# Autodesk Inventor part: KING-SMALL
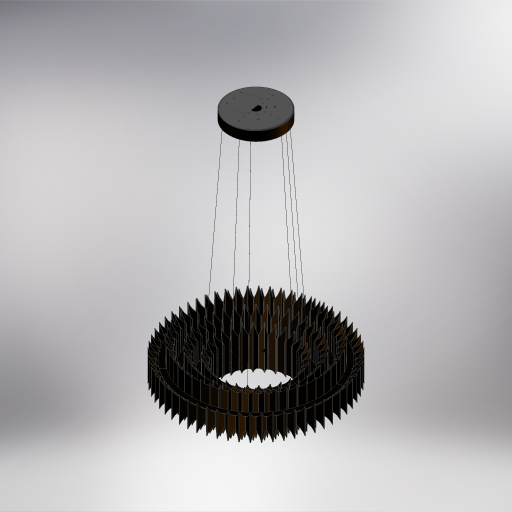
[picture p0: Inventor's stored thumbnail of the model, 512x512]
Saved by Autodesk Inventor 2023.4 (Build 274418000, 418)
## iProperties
Created: 2024-05
Part Number: KING-SMALL
Material: Generic
Document SubType Name: Modeling
Designer: JM
Density: 1 g/cm^3
Appearance: Default
Author: JM
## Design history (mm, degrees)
derived "KING-SMALL-0001-CUSTOMER.iam"
body "Solid1"
node "KINX-0008 - Ring size 4.iam:1::KINX0008.1 - Ring size 4.ipt:"
body "Solid2"
body "Solid3"
body "Solid4"
body "Solid5"
body "Solid6"
node "KINX-0006 - Ring size 2.iam:1::KINX0006.1 - Ring size 2.ipt:"
body "Solid7"
body "Solid8"
body "Solid9"
body "Solid10"
body "Solid11"
body "Solid12"
node "KINX-0007 - Ring size 3.iam:1::KINX0007.1 - Ring size 3.ipt:"
body "Solid13"
body "Solid14"
body "Solid15"
body "Solid16"
body "Solid17"
body "Solid18"
node "KINX-0011 - Ring top cover - size 4 - 811mm dia.ipt:1"
body "Solid19"
node "KINX-0010 - Ring top cover - size 3 - 663mm dia.ipt:1"
body "Solid20"
node "KINX-0009 - Ring top cover - size 2 - 517mm dia.ipt:1"
body "Solid21"
node "KINX-0011 - Ring top cover - size 4 - 811mm dia.ipt:2"
body "Solid22"
node "KINX-0010 - Ring top cover - size 3 - 663mm dia.ipt:2"
body "Solid23"
node "KINX-0009 - Ring top cover - size 2 - 517mm dia.ipt:2"
body "Solid24"
node "KINX-0011 - Ring top cover - size 4 - 811mm dia.ipt:3"
body "Solid25"
node "KINX-0010 - Ring top cover - size 3 - 663mm dia.ipt:3"
body "Solid26"
node "KINX-0009 - Ring top cover - size 2 - 517mm dia.ipt:3"
body "Solid27"
node "KINX-0011 - Ring top cover - size 4 - 811mm dia.ipt:4"
body "Solid28"
node "KINX-0010 - Ring top cover - size 3 - 663mm dia.ipt:4"
body "Solid29"
node "KINX-0009 - Ring top cover - size 2 - 517mm dia.ipt:4"
body "Solid30"
node "KINX-0011 - Ring top cover - size 4 - 811mm dia.ipt:5"
body "Solid31"
node "KINX-0010 - Ring top cover - size 3 - 663mm dia.ipt:5"
body "Solid32"
node "KINX-0009 - Ring top cover - size 2 - 517mm dia.ipt:5"
body "Solid33"
body "Solid34"
node "KINX-AS09 - Ceiling Rose - CUSTOMERCAD.iam:1::tensile-grip-0"
body "Solid35"
node "KINX-AS09 - Ceiling Rose - CUSTOMERCAD.iam:1::tensile-grip-0"
body "Solid36"
node "KINX-AS09 - Ceiling Rose - CUSTOMERCAD.iam:1::tensile-grip-0"
body "Solid37"
node "KINX-AS09 - Ceiling Rose - CUSTOMERCAD.iam:1::tensile-grip-0"
body "Solid38"
node "KINX-AS09 - Ceiling Rose - CUSTOMERCAD.iam:1::tensile-grip-0"
body "Solid39"
body "Solid40"
body "Solid41"
body "Solid42"
body "Solid43"
body "Solid44"
node "KINX-0001 (KNG-UNILF-02) - Inner leaves CUSTOMERCAD SMALL.ip"
body "Solid45"
node "KINX-0003 (KNG-UNILF-01) - Middle leaves CUSTOMERCAD INNER S"
body "Solid46"
node "KINX-0003 (KNG-UNILF-01) - Middle leaves CUSTOMERCAD SMALL.i"
body "Solid47"
node "KINX-0005 (KNG-UNILF-03) - Short outer leaves - CUSTOMERCAD "
body "Solid48"
node "KINX-0005 (KNG-UNILF-03) - Short outer leaves - CUSTOMERCAD "
body "Solid49"
node "KINX-0005 (KNG-UNILF-03) - Short outer leaves - CUSTOMERCAD "
body "Solid50"
node "KINX-0005 (KNG-UNILF-03) - Short outer leaves - CUSTOMERCAD "
body "Solid51"
node "KINX-0005 (KNG-UNILF-03) - Short outer leaves - CUSTOMERCAD "
body "Solid52"
node "KINX-0005 (KNG-UNILF-03) - Short outer leaves - CUSTOMERCAD "
body "Solid53"
node "KINX-0005 (KNG-UNILF-03) - Short outer leaves - CUSTOMERCAD "
body "Solid54"
node "KINX-0005 (KNG-UNILF-03) - Short outer leaves - CUSTOMERCAD "
body "Solid55"
node "KINX-0005 (KNG-UNILF-03) - Short outer leaves - CUSTOMERCAD "
body "Solid56"
node "KINX-0005 (KNG-UNILF-03) - Short outer leaves - CUSTOMERCAD "
body "Solid57"
node "KINX-0005 (KNG-UNILF-03) - Short outer leaves - CUSTOMERCAD "
body "Solid58"
node "KINX-0005 (KNG-UNILF-03) - Short outer leaves - CUSTOMERCAD "
body "Solid59"
node "KINX-0005 (KNG-UNILF-03) - Short outer leaves - CUSTOMERCAD "
body "Solid60"
node "KINX-0005 (KNG-UNILF-03) - Short outer leaves - CUSTOMERCAD "
body "Solid61"
node "KINX-0005 (KNG-UNILF-03) - Short outer leaves - CUSTOMERCAD "
body "Solid62"
node "KINX-0005 (KNG-UNILF-03) - Short outer leaves - CUSTOMERCAD "
body "Solid63"
node "KINX-0005 (KNG-UNILF-03) - Short outer leaves - CUSTOMERCAD "
body "Solid64"
node "KINX-0005 (KNG-UNILF-03) - Short outer leaves - CUSTOMERCAD "
body "Solid65"
node "KINX-0005 (KNG-UNILF-03) - Short outer leaves - CUSTOMERCAD "
body "Solid66"
node "KINX-0005 (KNG-UNILF-03) - Short outer leaves - CUSTOMERCAD "
body "Solid67"
node "KINX-0005 (KNG-UNILF-03) - Short outer leaves - CUSTOMERCAD "
body "Solid68"
node "KINX-0005 (KNG-UNILF-03) - Short outer leaves - CUSTOMERCAD "
body "Solid69"
node "KINX-0005 (KNG-UNILF-03) - Short outer leaves - CUSTOMERCAD "
body "Solid70"
node "KINX-0005 (KNG-UNILF-03) - Short outer leaves - CUSTOMERCAD "
body "Solid71"
node "KINX-0005 (KNG-UNILF-03) - Short outer leaves - CUSTOMERCAD "
body "Solid72"
node "KINX-0005 (KNG-UNILF-03) - Short outer leaves - CUSTOMERCAD "
body "Solid73"
node "KINX-0005 (KNG-UNILF-03) - Short outer leaves - CUSTOMERCAD "
body "Solid74"
node "KINX-0005 (KNG-UNILF-03) - Short outer leaves - CUSTOMERCAD "
body "Solid75"
node "KINX-0005 (KNG-UNILF-03) - Short outer leaves - CUSTOMERCAD "
body "Solid76"
node "KINX-0005 (KNG-UNILF-03) - Short outer leaves - CUSTOMERCAD "
body "Solid77"
node "KINX-0005 (KNG-UNILF-03) - Short outer leaves - CUSTOMERCAD "
body "Solid78"
node "KINX-0005 (KNG-UNILF-03) - Short outer leaves - CUSTOMERCAD "
body "Solid79"
node "KINX-0005 (KNG-UNILF-03) - Short outer leaves - CUSTOMERCAD "
body "Solid80"
node "KINX-0005 (KNG-UNILF-03) - Short outer leaves - CUSTOMERCAD "
body "Solid81"
node "KINX-0005 (KNG-UNILF-03) - Short outer leaves - CUSTOMERCAD "
body "Solid82"
node "KINX-0005 (KNG-UNILF-03) - Short outer leaves - CUSTOMERCAD "
body "Solid83"
node "KINX-0005 (KNG-UNILF-03) - Short outer leaves - CUSTOMERCAD "
body "Solid84"
node "KINX-0005 (KNG-UNILF-03) - Short outer leaves - CUSTOMERCAD "
body "Solid85"
node "KINX-0005 (KNG-UNILF-03) - Short outer leaves - CUSTOMERCAD "
body "Solid86"
node "KINX-0005 (KNG-UNILF-03) - Short outer leaves - CUSTOMERCAD "
body "Solid87"
node "KINX-0005 (KNG-UNILF-03) - Short outer leaves - CUSTOMERCAD "
body "Solid88"
node "KINX-0005 (KNG-UNILF-03) - Short outer leaves - CUSTOMERCAD "
body "Solid89"
node "KINX-0005 (KNG-UNILF-03) - Short outer leaves - CUSTOMERCAD "
body "Solid90"
node "KINX-0005 (KNG-UNILF-03) - Short outer leaves - CUSTOMERCAD "
body "Solid91"
node "KINX-0005 (KNG-UNILF-03) - Short outer leaves - CUSTOMERCAD "
body "Solid92"
node "KINX-0005 (KNG-UNILF-03) - Short outer leaves - CUSTOMERCAD "
body "Solid93"
node "KINX-0005 (KNG-UNILF-03) - Short outer leaves - CUSTOMERCAD "
body "Solid94"
node "KINX-0005 (KNG-UNILF-03) - Short outer leaves - CUSTOMERCAD "
body "Solid95"
node "KINX-0005 (KNG-UNILF-03) - Short outer leaves - CUSTOMERCAD "
body "Solid96"
node "KINX-0005 (KNG-UNILF-03) - Short outer leaves - CUSTOMERCAD "
body "Solid97"
node "KINX-0005 (KNG-UNILF-03) - Short outer leaves - CUSTOMERCAD "
body "Solid98"
node "KINX-0005 (KNG-UNILF-03) - Short outer leaves - CUSTOMERCAD "
body "Solid99"
node "KINX-0005 (KNG-UNILF-03) - Short outer leaves - CUSTOMERCAD "
body "Solid100"
node "KINX-0005 (KNG-UNILF-03) - Short outer leaves - CUSTOMERCAD "
body "Solid101"
node "KINX-0005 (KNG-UNILF-03) - Short outer leaves - CUSTOMERCAD "
body "Solid102"
node "KINX-0005 (KNG-UNILF-03) - Short outer leaves - CUSTOMERCAD "
body "Solid103"
node "KINX-0005 (KNG-UNILF-03) - Short outer leaves - CUSTOMERCAD "
body "Solid104"
node "KINX-0005 (KNG-UNILF-03) - Short outer leaves - CUSTOMERCAD "
body "Solid105"
node "KINX-0005 (KNG-UNILF-03) - Short outer leaves - CUSTOMERCAD "
body "Solid106"
node "KINX-0005 (KNG-UNILF-03) - Short outer leaves - CUSTOMERCAD "
body "Solid107"
node "KINX-0003 (KNG-UNILF-01) - Middle leaves CUSTOMERCAD SMALL.i"
body "Solid108"
node "KINX-0003 (KNG-UNILF-01) - Middle leaves CUSTOMERCAD SMALL.i"
body "Solid109"
node "KINX-0003 (KNG-UNILF-01) - Middle leaves CUSTOMERCAD SMALL.i"
body "Solid110"
node "KINX-0003 (KNG-UNILF-01) - Middle leaves CUSTOMERCAD SMALL.i"
body "Solid111"
node "KINX-0003 (KNG-UNILF-01) - Middle leaves CUSTOMERCAD SMALL.i"
body "Solid112"
node "KINX-0003 (KNG-UNILF-01) - Middle leaves CUSTOMERCAD SMALL.i"
body "Solid113"
node "KINX-0003 (KNG-UNILF-01) - Middle leaves CUSTOMERCAD SMALL.i"
body "Solid114"
node "KINX-0003 (KNG-UNILF-01) - Middle leaves CUSTOMERCAD SMALL.i"
body "Solid115"
node "KINX-0003 (KNG-UNILF-01) - Middle leaves CUSTOMERCAD SMALL.i"
body "Solid116"
node "KINX-0003 (KNG-UNILF-01) - Middle leaves CUSTOMERCAD SMALL.i"
body "Solid117"
node "KINX-0003 (KNG-UNILF-01) - Middle leaves CUSTOMERCAD SMALL.i"
body "Solid118"
node "KINX-0003 (KNG-UNILF-01) - Middle leaves CUSTOMERCAD SMALL.i"
body "Solid119"
node "KINX-0003 (KNG-UNILF-01) - Middle leaves CUSTOMERCAD SMALL.i"
body "Solid120"
node "KINX-0003 (KNG-UNILF-01) - Middle leaves CUSTOMERCAD SMALL.i"
body "Solid121"
node "KINX-0003 (KNG-UNILF-01) - Middle leaves CUSTOMERCAD SMALL.i"
body "Solid122"
node "KINX-0003 (KNG-UNILF-01) - Middle leaves CUSTOMERCAD SMALL.i"
body "Solid123"
node "KINX-0003 (KNG-UNILF-01) - Middle leaves CUSTOMERCAD SMALL.i"
body "Solid124"
node "KINX-0003 (KNG-UNILF-01) - Middle leaves CUSTOMERCAD SMALL.i"
body "Solid125"
node "KINX-0003 (KNG-UNILF-01) - Middle leaves CUSTOMERCAD SMALL.i"
body "Solid126"
node "KINX-0003 (KNG-UNILF-01) - Middle leaves CUSTOMERCAD SMALL.i"
body "Solid127"
node "KINX-0003 (KNG-UNILF-01) - Middle leaves CUSTOMERCAD SMALL.i"
body "Solid128"
node "KINX-0003 (KNG-UNILF-01) - Middle leaves CUSTOMERCAD SMALL.i"
body "Solid129"
node "KINX-0003 (KNG-UNILF-01) - Middle leaves CUSTOMERCAD SMALL.i"
body "Solid130"
node "KINX-0003 (KNG-UNILF-01) - Middle leaves CUSTOMERCAD SMALL.i"
body "Solid131"
node "KINX-0003 (KNG-UNILF-01) - Middle leaves CUSTOMERCAD SMALL.i"
body "Solid132"
node "KINX-0003 (KNG-UNILF-01) - Middle leaves CUSTOMERCAD SMALL.i"
body "Solid133"
node "KINX-0003 (KNG-UNILF-01) - Middle leaves CUSTOMERCAD SMALL.i"
body "Solid134"
node "KINX-0003 (KNG-UNILF-01) - Middle leaves CUSTOMERCAD SMALL.i"
body "Solid135"
node "KINX-0003 (KNG-UNILF-01) - Middle leaves CUSTOMERCAD SMALL.i"
body "Solid136"
node "KINX-0003 (KNG-UNILF-01) - Middle leaves CUSTOMERCAD SMALL.i"
body "Solid137"
node "KINX-0003 (KNG-UNILF-01) - Middle leaves CUSTOMERCAD SMALL.i"
body "Solid138"
node "KINX-0003 (KNG-UNILF-01) - Middle leaves CUSTOMERCAD SMALL.i"
body "Solid139"
node "KINX-0003 (KNG-UNILF-01) - Middle leaves CUSTOMERCAD SMALL.i"
body "Solid140"
node "KINX-0003 (KNG-UNILF-01) - Middle leaves CUSTOMERCAD SMALL.i"
body "Solid141"
node "KINX-0003 (KNG-UNILF-01) - Middle leaves CUSTOMERCAD SMALL.i"
body "Solid142"
node "KINX-0003 (KNG-UNILF-01) - Middle leaves CUSTOMERCAD SMALL.i"
body "Solid143"
node "KINX-0003 (KNG-UNILF-01) - Middle leaves CUSTOMERCAD SMALL.i"
body "Solid144"
node "KINX-0003 (KNG-UNILF-01) - Middle leaves CUSTOMERCAD SMALL.i"
body "Solid145"
node "KINX-0003 (KNG-UNILF-01) - Middle leaves CUSTOMERCAD SMALL.i"
body "Solid146"
node "KINX-0003 (KNG-UNILF-01) - Middle leaves CUSTOMERCAD SMALL.i"
body "Solid147"
node "KINX-0003 (KNG-UNILF-01) - Middle leaves CUSTOMERCAD SMALL.i"
body "Solid148"
node "KINX-0003 (KNG-UNILF-01) - Middle leaves CUSTOMERCAD SMALL.i"
body "Solid149"
node "KINX-0003 (KNG-UNILF-01) - Middle leaves CUSTOMERCAD SMALL.i"
body "Solid150"
node "KINX-0003 (KNG-UNILF-01) - Middle leaves CUSTOMERCAD SMALL.i"
body "Solid151"
node "KINX-0003 (KNG-UNILF-01) - Middle leaves CUSTOMERCAD SMALL.i"
body "Solid152"
node "KINX-0003 (KNG-UNILF-01) - Middle leaves CUSTOMERCAD SMALL.i"
body "Solid153"
node "KINX-0003 (KNG-UNILF-01) - Middle leaves CUSTOMERCAD SMALL.i"
body "Solid154"
node "KINX-0003 (KNG-UNILF-01) - Middle leaves CUSTOMERCAD SMALL.i"
body "Solid155"
node "KINX-0003 (KNG-UNILF-01) - Middle leaves CUSTOMERCAD SMALL.i"
body "Solid156"
node "KINX-0003 (KNG-UNILF-01) - Middle leaves CUSTOMERCAD INNER S"
body "Solid157"
node "KINX-0003 (KNG-UNILF-01) - Middle leaves CUSTOMERCAD INNER S"
body "Solid158"
node "KINX-0003 (KNG-UNILF-01) - Middle leaves CUSTOMERCAD INNER S"
body "Solid159"
node "KINX-0003 (KNG-UNILF-01) - Middle leaves CUSTOMERCAD INNER S"
body "Solid160"
node "KINX-0003 (KNG-UNILF-01) - Middle leaves CUSTOMERCAD INNER S"
body "Solid161"
node "KINX-0003 (KNG-UNILF-01) - Middle leaves CUSTOMERCAD INNER S"
body "Solid162"
node "KINX-0003 (KNG-UNILF-01) - Middle leaves CUSTOMERCAD INNER S"
body "Solid163"
node "KINX-0003 (KNG-UNILF-01) - Middle leaves CUSTOMERCAD INNER S"
body "Solid164"
node "KINX-0003 (KNG-UNILF-01) - Middle leaves CUSTOMERCAD INNER S"
body "Solid165"
node "KINX-0003 (KNG-UNILF-01) - Middle leaves CUSTOMERCAD INNER S"
body "Solid166"
node "KINX-0003 (KNG-UNILF-01) - Middle leaves CUSTOMERCAD INNER S"
body "Solid167"
node "KINX-0003 (KNG-UNILF-01) - Middle leaves CUSTOMERCAD INNER S"
body "Solid168"
node "KINX-0003 (KNG-UNILF-01) - Middle leaves CUSTOMERCAD INNER S"
body "Solid169"
node "KINX-0003 (KNG-UNILF-01) - Middle leaves CUSTOMERCAD INNER S"
body "Solid170"
node "KINX-0003 (KNG-UNILF-01) - Middle leaves CUSTOMERCAD INNER S"
body "Solid171"
node "KINX-0003 (KNG-UNILF-01) - Middle leaves CUSTOMERCAD INNER S"
body "Solid172"
node "KINX-0003 (KNG-UNILF-01) - Middle leaves CUSTOMERCAD INNER S"
body "Solid173"
node "KINX-0003 (KNG-UNILF-01) - Middle leaves CUSTOMERCAD INNER S"
body "Solid174"
node "KINX-0003 (KNG-UNILF-01) - Middle leaves CUSTOMERCAD INNER S"
body "Solid175"
node "KINX-0003 (KNG-UNILF-01) - Middle leaves CUSTOMERCAD INNER S"
body "Solid176"
node "KINX-0003 (KNG-UNILF-01) - Middle leaves CUSTOMERCAD INNER S"
body "Solid177"
node "KINX-0003 (KNG-UNILF-01) - Middle leaves CUSTOMERCAD INNER S"
body "Solid178"
node "KINX-0003 (KNG-UNILF-01) - Middle leaves CUSTOMERCAD INNER S"
body "Solid179"
node "KINX-0003 (KNG-UNILF-01) - Middle leaves CUSTOMERCAD INNER S"
body "Solid180"
node "KINX-0003 (KNG-UNILF-01) - Middle leaves CUSTOMERCAD INNER S"
body "Solid181"
node "KINX-0003 (KNG-UNILF-01) - Middle leaves CUSTOMERCAD INNER S"
body "Solid182"
node "KINX-0003 (KNG-UNILF-01) - Middle leaves CUSTOMERCAD INNER S"
body "Solid183"
node "KINX-0003 (KNG-UNILF-01) - Middle leaves CUSTOMERCAD INNER S"
body "Solid184"
node "KINX-0003 (KNG-UNILF-01) - Middle leaves CUSTOMERCAD INNER S"
body "Solid185"
node "KINX-0003 (KNG-UNILF-01) - Middle leaves CUSTOMERCAD INNER S"
body "Solid186"
node "KINX-0003 (KNG-UNILF-01) - Middle leaves CUSTOMERCAD INNER S"
body "Solid187"
node "KINX-0003 (KNG-UNILF-01) - Middle leaves CUSTOMERCAD INNER S"
body "Solid188"
node "KINX-0003 (KNG-UNILF-01) - Middle leaves CUSTOMERCAD INNER S"
body "Solid189"
node "KINX-0003 (KNG-UNILF-01) - Middle leaves CUSTOMERCAD INNER S"
body "Solid190"
node "KINX-0003 (KNG-UNILF-01) - Middle leaves CUSTOMERCAD INNER S"
body "Solid191"
node "KINX-0003 (KNG-UNILF-01) - Middle leaves CUSTOMERCAD INNER S"
body "Solid192"
node "KINX-0003 (KNG-UNILF-01) - Middle leaves CUSTOMERCAD INNER S"
body "Solid193"
node "KINX-0003 (KNG-UNILF-01) - Middle leaves CUSTOMERCAD INNER S"
body "Solid194"
node "KINX-0003 (KNG-UNILF-01) - Middle leaves CUSTOMERCAD INNER S"
body "Solid195"
node "KINX-0001 (KNG-UNILF-02) - Inner leaves CUSTOMERCAD SMALL.ip"
body "Solid196"
node "KINX-0001 (KNG-UNILF-02) - Inner leaves CUSTOMERCAD SMALL.ip"
body "Solid197"
node "KINX-0001 (KNG-UNILF-02) - Inner leaves CUSTOMERCAD SMALL.ip"
body "Solid198"
node "KINX-0001 (KNG-UNILF-02) - Inner leaves CUSTOMERCAD SMALL.ip"
body "Solid199"
node "KINX-0001 (KNG-UNILF-02) - Inner leaves CUSTOMERCAD SMALL.ip"
body "Solid200"
node "KINX-0001 (KNG-UNILF-02) - Inner leaves CUSTOMERCAD SMALL.ip"
body "Solid201"
node "KINX-0001 (KNG-UNILF-02) - Inner leaves CUSTOMERCAD SMALL.ip"
body "Solid202"
node "KINX-0001 (KNG-UNILF-02) - Inner leaves CUSTOMERCAD SMALL.ip"
body "Solid203"
node "KINX-0001 (KNG-UNILF-02) - Inner leaves CUSTOMERCAD SMALL.ip"
body "Solid204"
node "KINX-0001 (KNG-UNILF-02) - Inner leaves CUSTOMERCAD SMALL.ip"
body "Solid205"
node "KINX-0001 (KNG-UNILF-02) - Inner leaves CUSTOMERCAD SMALL.ip"
body "Solid206"
node "KINX-0001 (KNG-UNILF-02) - Inner leaves CUSTOMERCAD SMALL.ip"
body "Solid207"
node "KINX-0001 (KNG-UNILF-02) - Inner leaves CUSTOMERCAD SMALL.ip"
body "Solid208"
node "KINX-0001 (KNG-UNILF-02) - Inner leaves CUSTOMERCAD SMALL.ip"
body "Solid209"
node "KINX-0001 (KNG-UNILF-02) - Inner leaves CUSTOMERCAD SMALL.ip"
body "Solid210"
node "KINX-0001 (KNG-UNILF-02) - Inner leaves CUSTOMERCAD SMALL.ip"
body "Solid211"
node "KINX-0001 (KNG-UNILF-02) - Inner leaves CUSTOMERCAD SMALL.ip"
body "Solid212"
node "KINX-0001 (KNG-UNILF-02) - Inner leaves CUSTOMERCAD SMALL.ip"
body "Solid213"
node "KINX-0001 (KNG-UNILF-02) - Inner leaves CUSTOMERCAD SMALL.ip"
body "Solid214"
node "KINX-0001 (KNG-UNILF-02) - Inner leaves CUSTOMERCAD SMALL.ip"
body "Solid215"
node "KINX-0001 (KNG-UNILF-02) - Inner leaves CUSTOMERCAD SMALL.ip"
body "Solid216"
node "KINX-0001 (KNG-UNILF-02) - Inner leaves CUSTOMERCAD SMALL.ip"
body "Solid217"
node "KINX-0001 (KNG-UNILF-02) - Inner leaves CUSTOMERCAD SMALL.ip"
body "Solid218"
node "KINX-0001 (KNG-UNILF-02) - Inner leaves CUSTOMERCAD SMALL.ip"
body "Solid219"
node "KINX-0001 (KNG-UNILF-02) - Inner leaves CUSTOMERCAD SMALL.ip"
body "Solid220"
node "KINX-0001 (KNG-UNILF-02) - Inner leaves CUSTOMERCAD SMALL.ip"
body "Solid221"
node "KINX-0001 (KNG-UNILF-02) - Inner leaves CUSTOMERCAD SMALL.ip"
body "Solid222"
node "KINX-0001 (KNG-UNILF-02) - Inner leaves CUSTOMERCAD SMALL.ip"
body "Solid223"
node "KINX-0001 (KNG-UNILF-02) - Inner leaves CUSTOMERCAD SMALL.ip"
body "Solid224"
node "turned-screw-cover.ipt:1"
body "Solid225"
node "finial-15mm.ipt:1"
body "Solid226"
node "turned-screw-cover.ipt:2"
body "Solid227"
node "finial-15mm.ipt:2"
body "Solid228"
node "turned-screw-cover.ipt:3"
body "Solid229"
node "finial-15mm.ipt:3"
body "Solid230"
node "turned-screw-cover.ipt:4"
body "Solid231"
node "finial-15mm.ipt:4"
body "Solid232"
node "turned-screw-cover.ipt:5"
body "Solid233"
node "finial-15mm.ipt:5"
body "Solid234"
node "turned-screw-cover.ipt:6"
body "Solid235"
node "finial-15mm.ipt:6"
body "Solid236"
node "turned-screw-cover.ipt:7"
body "Solid237"
node "finial-15mm.ipt:7"
body "Solid238"
node "turned-screw-cover.ipt:8"
body "Solid239"
node "finial-15mm.ipt:8"
body "Solid240"
node "turned-screw-cover.ipt:9"
body "Solid241"
node "finial-15mm.ipt:9"
body "Solid242"
node "turned-screw-cover.ipt:10"
body "Solid243"
node "finial-15mm.ipt:10"
body "Solid244"
node "Tensile-cable-small.ipt:1"
body "Solid245"
node "Tensile-cable-small.ipt:3"
body "Solid246"
node "Tensile-cable-small.ipt:5"
body "Solid247"
node "Tensile-cable-small.ipt:7"
body "Solid248"
node "Tensile-cable-small.ipt:9"
body "Solid249"
node "Tensile-cable-small.ipt:10"
body "Solid250"
